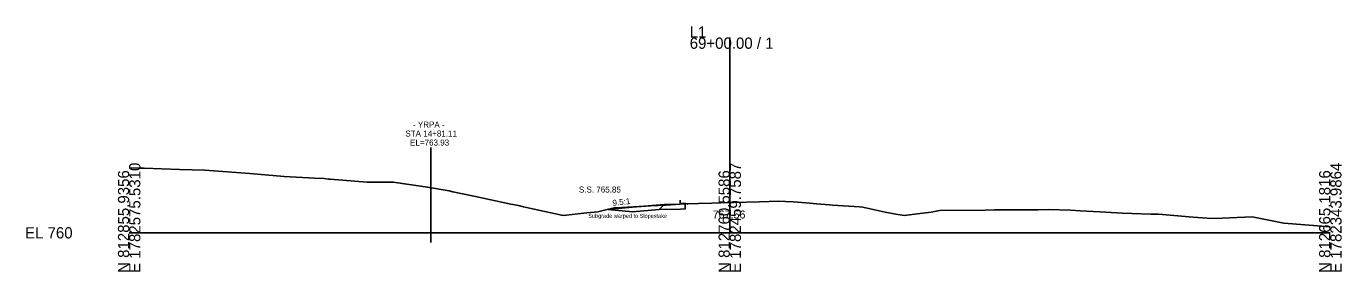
# Model space of a CAD drawing. Extents: x 5574 to 10203, y -10 to 9546.
# Drawn here: x 7574.3 to 7902.8, y 6490.3 to 6551.5 of the extents above; entities that cross this region are included whole.
import ezdxf

# ---------------------------------------------------------------- set-up
doc = ezdxf.new("R2010")
doc.units = 0
for name, color, linetype in [('Exist Cross Section Cell', 7, 'Continuous'), ('Exist XS Center Line Elevation Label', 7, 'Continuous'), ('Exist XS Ground Line', 7, 'Continuous'), ('Prop XS Ditch Slope Text', 7, 'Continuous'), ('Prop XS Dump Level', 7, 'Continuous'), ('Prop XS Earthwork Shape', 7, 'Continuous'), ('Prop XS EOT Tick Mark', 7, 'Continuous'), ('Prop XS Finish Grade', 7, 'Continuous'), ('Prop XS Finish Grade Paved Shoulder', 7, 'Continuous'), ('Prop XS Finish Grade Pavement', 7, 'Continuous'), ('Prop XS Hydro Typical Ditch Data', 7, 'Continuous'), ('Prop XS Pvmt Edge Slope', 7, 'Continuous'), ('Prop XS SS Elevation Text', 7, 'Continuous'), ('Prop XS Subgrade Earthwork', 7, 'Continuous'), ('Prop XS Vertical Lines Alignments', 7, 'Continuous'), ('Scratch_Level_3', 7, 'Continuous'), ('Scratch_Level_6', 7, 'Continuous')]:
    doc.layers.add(name, color=color, linetype=linetype)

msp = doc.modelspace()

# ---------------------------------------------------------------- linework, layer by layer
at = {"layer": 'Exist Cross Section Cell'}
for p, q in [((7750, 6500), (7750, 6548.7)), ((7600, 6500), (7750, 6500)), ((7750, 6500), (7900, 6500))]:
    msp.add_line(p, q, dxfattribs=at)
at = {"layer": 'Exist XS Ground Line'}
for p, q in [((7600, 6516.23), (7602.86, 6516.15)), ((7602.86, 6516.15), (7603.29, 6516.13)), ((7603.29, 6516.13), (7603.71, 6516.1)), ((7603.71, 6516.1), (7612.6, 6515.79)), ((7612.6, 6515.79), (7618.93, 6515.62)), ((7618.93, 6515.62), (7630.16, 6514.8)), ((7630.16, 6514.8), (7638.71, 6514.04)), ((7638.71, 6514.04), (7646.32, 6513.62)), ((7646.32, 6513.62), (7648.66, 6513.51)), ((7648.66, 6513.51), (7649.77, 6513.4)), ((7649.77, 6513.4), (7650.23, 6513.35)), ((7650.23, 6513.35), (7659.43, 6512.64)), ((7659.43, 6512.64), (7665.92, 6512.64)), ((7665.92, 6512.64), (7674.47, 6511.4)), ((7674.47, 6511.4), (7679.93, 6510.48)), ((7679.93, 6510.48), (7680.83, 6510.23)), ((7680.83, 6510.23), (7686.52, 6509.07)), ((7686.52, 6509.07), (7695.32, 6507.11)), ((7695.32, 6507.11), (7697.26, 6506.78)), ((7697.26, 6506.78), (7698.47, 6506.48)), ((7698.47, 6506.48), (7708.36, 6504.28)), ((7709.89, 6504.52), (7714.29, 6505.02)), ((7714.29, 6505.02), (7717.08, 6505.27)), ((7717.08, 6505.27), (7719.41, 6505.79)), ((7719.41, 6505.79), (7721.22, 6506.26)), ((7721.22, 6506.26), (7723.06, 6506.34)), ((7723.06, 6506.34), (7730.2, 6506.73)), ((7730.2, 6506.73), (7734.08, 6506.92)), ((7734.08, 6506.92), (7736.42, 6507.07)), ((7736.42, 6507.07), (7738.89, 6507.22)), ((7738.89, 6507.22), (7745.55, 6507.42)), ((7745.55, 6507.42), (7750, 6507.56)), ((7750, 6507.56), (7751.03, 6507.59)), ((7751.03, 6507.59), (7757.46, 6507.73)), ((7757.46, 6507.73), (7762.29, 6507.85)), ((7762.29, 6507.85), (7763.95, 6507.78)), ((7763.95, 6507.78), (7765.89, 6507.7)), ((7765.89, 6507.7), (7770.01, 6507.35)), ((7770.01, 6507.35), (7771.64, 6507.22)), ((7771.64, 6507.22), (7774.93, 6506.98)), ((7774.93, 6506.98), (7775.7, 6506.92)), ((7775.7, 6506.92), (7782.39, 6506.44)), ((7782.39, 6506.44), (7783.25, 6506.37)), ((7783.25, 6506.37), (7785.09, 6505.98)), ((7785.09, 6505.98), (7788.78, 6505.18)), ((7788.78, 6505.18), (7791.47, 6504.66)), ((7796.93, 6504.71), (7800.34, 6505.12)), ((7800.34, 6505.12), (7802.42, 6505.54)), ((7802.42, 6505.54), (7813.83, 6505.66)), ((7813.83, 6505.66), (7816.16, 6505.73)), ((7816.16, 6505.73), (7817.75, 6505.69)), ((7817.75, 6505.69), (7827, 6505.69)), ((7827, 6505.69), (7829.5, 6505.84)), ((7829.5, 6505.84), (7835.1, 6505.64)), ((7835.1, 6505.64), (7837.56, 6505.48)), ((7837.56, 6505.48), (7842.46, 6505.25)), ((7842.46, 6505.25), (7848.13, 6504.86)), ((7708.36, 6504.28), (7709.89, 6504.52)), ((7791.47, 6504.66), (7793.57, 6504.32)), ((7793.57, 6504.32), (7796.93, 6504.71)), ((7848.13, 6504.86), (7850.46, 6504.79)), ((7850.46, 6504.79), (7855.21, 6504.63)), ((7855.21, 6504.63), (7857.07, 6504.62)), ((7857.07, 6504.62), (7865.72, 6503.91)), ((7865.72, 6503.91), (7869.28, 6503.61)), ((7869.28, 6503.61), (7871.15, 6503.58)), ((7871.15, 6503.58), (7880.48, 6503.99)), ((7880.48, 6503.99), (7888.01, 6502.47)), ((7888.01, 6502.47), (7888.43, 6502.39)), ((7888.43, 6502.39), (7889.49, 6502.32)), ((7889.49, 6502.32), (7900, 6501.5))]:
    msp.add_line(p, q, dxfattribs=at)
at = {"layer": 'Prop XS Dump Level'}
msp.add_line((7739.01, 6507.34), (7737.63, 6507.31), dxfattribs=at)
msp.add_line((7739.01, 6507.34), (7737.63, 6507.31), dxfattribs=at)
at = {"layer": 'Prop XS Earthwork Shape'}
msp.add_lwpolyline([(7719.64, 6505.85), (7721.22, 6506.26), (7723.06, 6506.34), (7730.2, 6506.73), (7734.08, 6506.92), (7736.42, 6507.07), (7738.9, 6507.22), (7738.9, 6505.97), (7737.67, 6505.93), (7732.34, 6505.77), (7725.72, 6505.24)], close=True, dxfattribs=at)
at = {"layer": 'Prop XS EOT Tick Mark'}
msp.add_line((7737.63, 6507.18), (7737.63, 6508.18), dxfattribs=at)
at = {"layer": 'Prop XS Finish Grade'}
for p, q in [((7725.63, 6506.42), (7719.64, 6505.85)), ((7730.63, 6506.82), (7725.63, 6506.42)), ((7733.63, 6507.06), (7730.63, 6506.82))]:
    msp.add_line(p, q, dxfattribs=at)
at = {"layer": 'Prop XS Finish Grade Paved Shoulder'}
msp.add_line((7737.63, 6507.18), (7733.63, 6507.06), dxfattribs=at)
at = {"layer": 'Prop XS Finish Grade Pavement'}
msp.add_line((7738.9, 6507.22), (7737.63, 6507.18), dxfattribs=at)
at = {"layer": 'Prop XS Hydro Typical Ditch Data'}
msp.add_line((7725.63, 6506.42), (7719.64, 6505.85), dxfattribs=at)
at = {"layer": 'Prop XS Pvmt Edge Slope'}
msp.add_line((7733.63, 6507.06), (7732.34, 6505.77), dxfattribs=at)
at = {"layer": 'Prop XS Subgrade Earthwork'}
for p, q in [((7725.72, 6505.24), (7719.64, 6505.85)), ((7732.34, 6505.77), (7725.72, 6505.24)), ((7737.67, 6505.93), (7732.34, 6505.77)), ((7738.9, 6505.97), (7737.67, 6505.93)), ((7738.9, 6505.97), (7738.9, 6507.22))]:
    msp.add_line(p, q, dxfattribs=at)
at = {"layer": 'Prop XS Vertical Lines Alignments'}
msp.add_line((7675.31, 6521.26), (7675.31, 6497.56), dxfattribs=at)
at = {"layer": 'Scratch_Level_3'}
for p, q in [((7725.63, 6506.42), (7719.64, 6505.85)), ((7719.64, 6505.85), (7725.72, 6505.24)), ((7730.63, 6506.82), (7725.63, 6506.42)), ((7725.72, 6505.24), (7732.34, 6505.77)), ((7733.63, 6507.06), (7730.63, 6506.82)), ((7732.34, 6505.77), (7733.63, 6507.06))]:
    msp.add_line(p, q, dxfattribs=at)
at = {"layer": 'Scratch_Level_6'}
msp.add_lwpolyline([(7727.91, 6506.6), (7730.2, 6506.73), (7734.08, 6506.92), (7736.42, 6507.07), (7738.9, 6507.22), (7738.9, 6505.97), (7737.67, 6505.93), (7732.34, 6505.77), (7725.72, 6505.24), (7719.64, 6505.85), (7725.63, 6506.42)], close=True, dxfattribs=at)

# ---------------------------------------------------------------- texts
at = {"layer": 'Exist Cross Section Cell'}
for s, p in [('L1', (7740, 6548.7)), ('69+00.00 / 1', (7740, 6545.9)), ('EL 760', (7574, 6498.6))]:
    msp.add_text(s, height=2.8, dxfattribs=at).set_placement(p)
for s, p in [('N 812855.9356', (7600, 6490)), ('E 1782575.5310', (7602.8, 6490)), ('N 812760.5586', (7750, 6490)), ('E 1782459.7587', (7752.8, 6490)), ('N 812665.1816', (7900, 6490)), ('E 1782343.9864', (7902.8, 6490))]:
    msp.add_text(s, height=2.8, rotation=90, dxfattribs=at).set_placement(p)
at = {"layer": 'Exist XS Center Line Elevation Label'}
msp.add_text('767.56', height=2, dxfattribs=at).set_placement((7745.73, 6503.56))
at = {"layer": 'Prop XS Ditch Slope Text'}
msp.add_text('9.5:1', height=1.5, rotation=6.6311, dxfattribs=at).set_placement((7720.8, 6506.68))
at = {"layer": 'Prop XS Dump Level'}
for s, height, p in [('Case4', 0.04, (7725.63, 6506.38)), ('Eop', 0.3, (7738.9, 6506.92)), ('Subgrade warped to Slopestake', 1, (7714.68, 6503.72))]:
    msp.add_text(s, height=height, dxfattribs=at).set_placement(p)
at = {"layer": 'Prop XS SS Elevation Text'}
msp.add_text('S.S. 765.85', height=1.5, dxfattribs=at).set_placement((7712.32, 6510.04))
at = {"layer": 'Prop XS Vertical Lines Alignments'}
for s, p in [('STA 14+81.11', (7668.99, 6524.01)), ('- YRPA -', (7670.88, 6526.26)), ('EL=763.93', (7670.16, 6521.76))]:
    msp.add_text(s, height=1.5, dxfattribs=at).set_placement(p)

doc.saveas('drawing.dxf')
